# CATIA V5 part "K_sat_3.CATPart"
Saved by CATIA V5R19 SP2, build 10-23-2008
Part number: sat 3
Source: Unknown
Material "Aucun"
Bounding box of the stored display mesh (mm): x -63.515 to 63.515, y -63.573 to 63.573, z -18.921 to 41.193
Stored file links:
  G:\Khaled_CFAO_2011\ST2M\ST2M_GR1\mponsin\Khaled\CAD_ThinkMOTION\K_sat_3.CATPart
  C:\Program Files\Dassault Systemes\B20\win_b64\startup\materials\French\Catalog.CATMaterial
  C:\Users\Socar\Documents\thinkmotion\Final\Diff2.CATProduct
  G:\Khaled_CFAO_2011\ST2M\ST2M_GR1\mponsin\Khaled\CAD_ThinkMOTION\K_mponsin.CATProduct
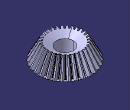
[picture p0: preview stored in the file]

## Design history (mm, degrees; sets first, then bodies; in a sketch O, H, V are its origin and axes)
Parameters
  Z1 = 30 {= External.Zs}
  delta = 26.5651 deg {= atan(External.Zs /External.Zp )}
  a = 20 deg
  m = 4 mm {= External.Module}
  ld = 44.7214 mm {= m *Z1 /(3*2*sin(delta ))}
  dZ = 0 mm
  p = 12.5664 mm {= m * PI}
  rp = 60 mm {= m * Z1 / 2}
  rc = 67.082 mm {= rp / cos( delta )}
  rb = 63.0365 mm {= rc * cos( a )}
  lc = 150 mm {= rc / sin( delta )}
  ha = 4 mm {= m}
  hf = 5 mm {= 1.25 * m}
  rr = 1.4608 mm {= Set2.Offset * 0.7763}
  tc = -0.7576 deg
  ratio = 0.666667 {= 1 - ld / lc / cos( delta )}
External parameters (linked from other documents)
  External.Zp = 60
  External.Zs = 30
  External.Module = 4 mm
Intersect1 "coin de fond": ToIntersect1 Project1, ToIntersect2 Circle4
Point1: type OnCurve, Support Line7, Length 5 {= hf}
Set1 "cones primitifs"
  Line1 "Axe Z": stored without definition
  Point2 "sommet arriere": (0, 0, -30 {= dZ - rp * tan( delta )})
  Point3 "sommet avant": type OnCurve, Support Line1, RefPoint Point2, Length 150 {= lc}
  Line2: type PtPt, FirstPoint Point2, SecondPoint Point3
  Line3: type Angle, RefPoint Point3, Curve Line2, Support zx-plane, Start 0, End 134.1641 {= lc * cos( delta )}, Angle -26.5651 {= -delta}
  Line4: type PtPt, FirstPoint Point2, SecondPoint vertex of Line3, Start 0
  Plane1 "plan_primitif": type OffsetPt, RefPlane xy-plane, RefPoint vertex of Line3
  Intersect2: ToIntersect1 Plane1, ToIntersect2 Line2
  Circle1 "arc primitif": type CtrPt, Start 0, End 30, Center Intersect2, Support Plane1, RefPoint vertex of Line3
  Circle2 "cercle primitif": type CtrRad, Start 0, End 90, Center Intersect2, Support Plane1, Radius 60 {= rp}, FirstDirection (1, 0, 0)
Set2 "profil dent"
  Point4 "point 0": type OnPlane, Support Plane2, RefPoint Point2, H 63.0365, V 0, Direction (1, 0, 0)
  Point5 "point 1": type OnPlane, Support Plane2, RefPoint Point2, H 66.0709, V 0.6451, Direction (1, 0, 0)
  Point6 "point 2": type OnPlane, Support Plane2, RefPoint Point2, H 74.278, V 5.0092, Direction (1, 0, 0)
  Point7 "point 3": type OnPlane, Support Plane2, RefPoint Point2, H 85.116, V 16.077, Direction (1, 0, 0)
  Curve1: Elements (Point4; Point5; Point6; Point7)
  Extrapol1: ToExtrapol Point4, Support Curve1, Length 8 {= 2 * m}
  Plane2: type Normal, Curve Line3, RefPoint Point2
  Symmetry1: Reference vertex of Line3, ToTransfor Point2
  Line5: type PtPt, FirstPoint Point2, SecondPoint Symmetry1
  Point8: type OnCurve, Support Line5, Ratio 0.25
  Line6: type PtPt, FirstPoint Point8, SecondPoint vertex of Line5
  Revol1: Element1 Line6, Line Line1, Angle1 0
  Project1: ToProject Extrapol1, Support Revol1, Direction Line3
  Intersect3: ToIntersect1 Circle1, ToIntersect2 Project1
  Plane3 "plan contact": type 1Line1Pt, RefPoint Intersect3, Line Line1
  Circle3 "cercle primitif": type CtrPt, Start 3 {= 90deg / Z1}, End -3 {= -90deg / Z1}, Center Intersect2, Support Plane1, RefPoint Intersect3
  Plane4 "plan median": type 1Line1Pt, RefPoint vertex of Circle3, Line Line1
  Line7 "droite debut": type PtPt, FirstPoint vertex of Circle3, SecondPoint Point2
  Plane5 "plan_fond": type OffsetPt, RefPlane xy-plane, RefPoint Point1
  Intersect4: ToIntersect1 Plane5, ToIntersect2 Line2
  Circle4 "cercle de fond": type CtrPt, Start 0, End 30, Center Intersect4, Support Plane5, RefPoint Point1
  Point9: type OnCurve, Support Line7, Length -4 {= -ha}
  Plane6 "plan_tete": type OffsetPt, RefPlane xy-plane, RefPoint Point9
  Intersect5: ToIntersect1 Plane6, ToIntersect2 Line2
  Circle5 "cercle de tete": type CtrPt, Start 0, End 30, Center Intersect5, Support Plane6, RefPoint Point9
  Split1 "segment flanc": ToCut Project1, Cutting Plane5
  Split2 "segment fond": ToCut Circle4, Cutting Project1
  Corner1: Element1 Split1, Element2 Split2, Support Revol1, Radius 1.4301 {= Set2.Offset * 0.76}
  Symmetry2: Reference Plane4, ToTransfor Corner1
  Trim1: Element1 Corner1, Element2 Circle5
  Trim2: Element1 Trim1, Element2 Symmetry2
Set3 "surface dent"
  Point10 "fin denture": type OnCurve, Support Line3, Length 44.7214 {= ld}
  Scaling1: Reference Point3, Ratio 0.666667 {= ratio}, ToTransfor Trim2
  Line8: type PtPt, FirstPoint vertex of Scaling1, SecondPoint Point1
  Line9: type PtPt, FirstPoint vertex of Scaling1, SecondPoint vertex of Trim2
  Loft1: Sections (Trim2; Scaling1), Guides (Line8; Line9)
  CircPattern1: of Loft1, instances 30 {= Z1}, angular step 12 {= 360.0*1 deg/CircPattern1.AngularNumber}, axis from Line2
Set4 "flanc dent"
  CircPattern2: of Trim2, instances 30 {= Z1}, angular step 12 {= 360.0*1 deg/CircPattern2.AngularNumber}, axis from Line2
  Join1: Elements (CircPattern2; Trim2)
  Split3: ToCut Revol1, Cutting Join1
  Scaling2: Reference Point3, Ratio 0.666667 {= ratio}, ToTransfor Split3
  Fill1: Boundary edge of Scaling2
  Join2: Elements (Split3; CircPattern1; Scaling2; Fill1; Loft1)
Body1 (main body)
  Sketch1 on zx-plane, origin (0, 0, 0), H (-1, 0, 0), V (0, 0, 1)
    point P1 (-30, -15)
    line L1 (0, 0) -> (0, -18.9213)
    line L2 (0, -18.9213) -> (-30, -18.9213)
    line L3 (-30, -18.9213) -> (-30, -15)
    reference projected point E1 (-30, -15) from Point8
    line L4 (-30, -15) -> (-60, 0)
    point P5 (-60, 0)
    line L5 (0, 0) -> (-60, 0)
    reference projected point E2 (-60, 0) from vertex of Line4
    horizontal: L2 H, L5 H
    vertical: L1 V, L3 V
    coincidence: P1 E1, L1 V, P5 E2
  Shaft1: profile Sketch1, axis Line1, angle 360
  CloseSurface1: CloseElement Join2
  Sketch2 on xy-plane, origin (0, 0, 0), H (1, 0, 0), V (0, 1, 0)
    circle A1 centre (0, 0) radius 20
    radius A1 = 20
  Pocket1: profile Sketch2, direction (0, 0, 1), through (limit type 6), opposite side through (limit type 6)
  Body2
    Sketch3 on zx-plane, origin (0, 0, 0), H (-1, 0, 0), V (0, 0, 1)
      line L1 (0, -30) -> (333.9525, -10)
      point P1 (0, -30)
      point P2 (333.9525, -10)
      line L2 (333.9525, -10) -> (30, -10)
      point P3 (333.9525, -10)
      line L3 (30, -10) -> (30, -20)
      line L4 (30, -20) -> (0, -20)
      point P6 (0, -20)
      line L5 (0, -20) -> (0, -30)
      reference projected point E1 (0, -30) from Point2
      length L3 = 10
      length L4 = 30
      distance L2 H = 10
      length L2 = 303.9525
      coincidence: P1 V, P3 L1, P6 V, P2 P3, P1 E1
      horizontal: L2 H, L4 H
      vertical: L3 V, L5 V
    Shaft2: profile Sketch3, axis Sketch3.L5, angle 360
  Remove1: tool Body2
